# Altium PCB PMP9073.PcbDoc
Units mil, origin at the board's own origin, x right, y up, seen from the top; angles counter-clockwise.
Board outline 2100 x 1500 mil, 2 copper layers (Top Layer, Bottom Layer), stack 62 mil thick; 21 components, 11 nets, 42 pads, 0 vias.
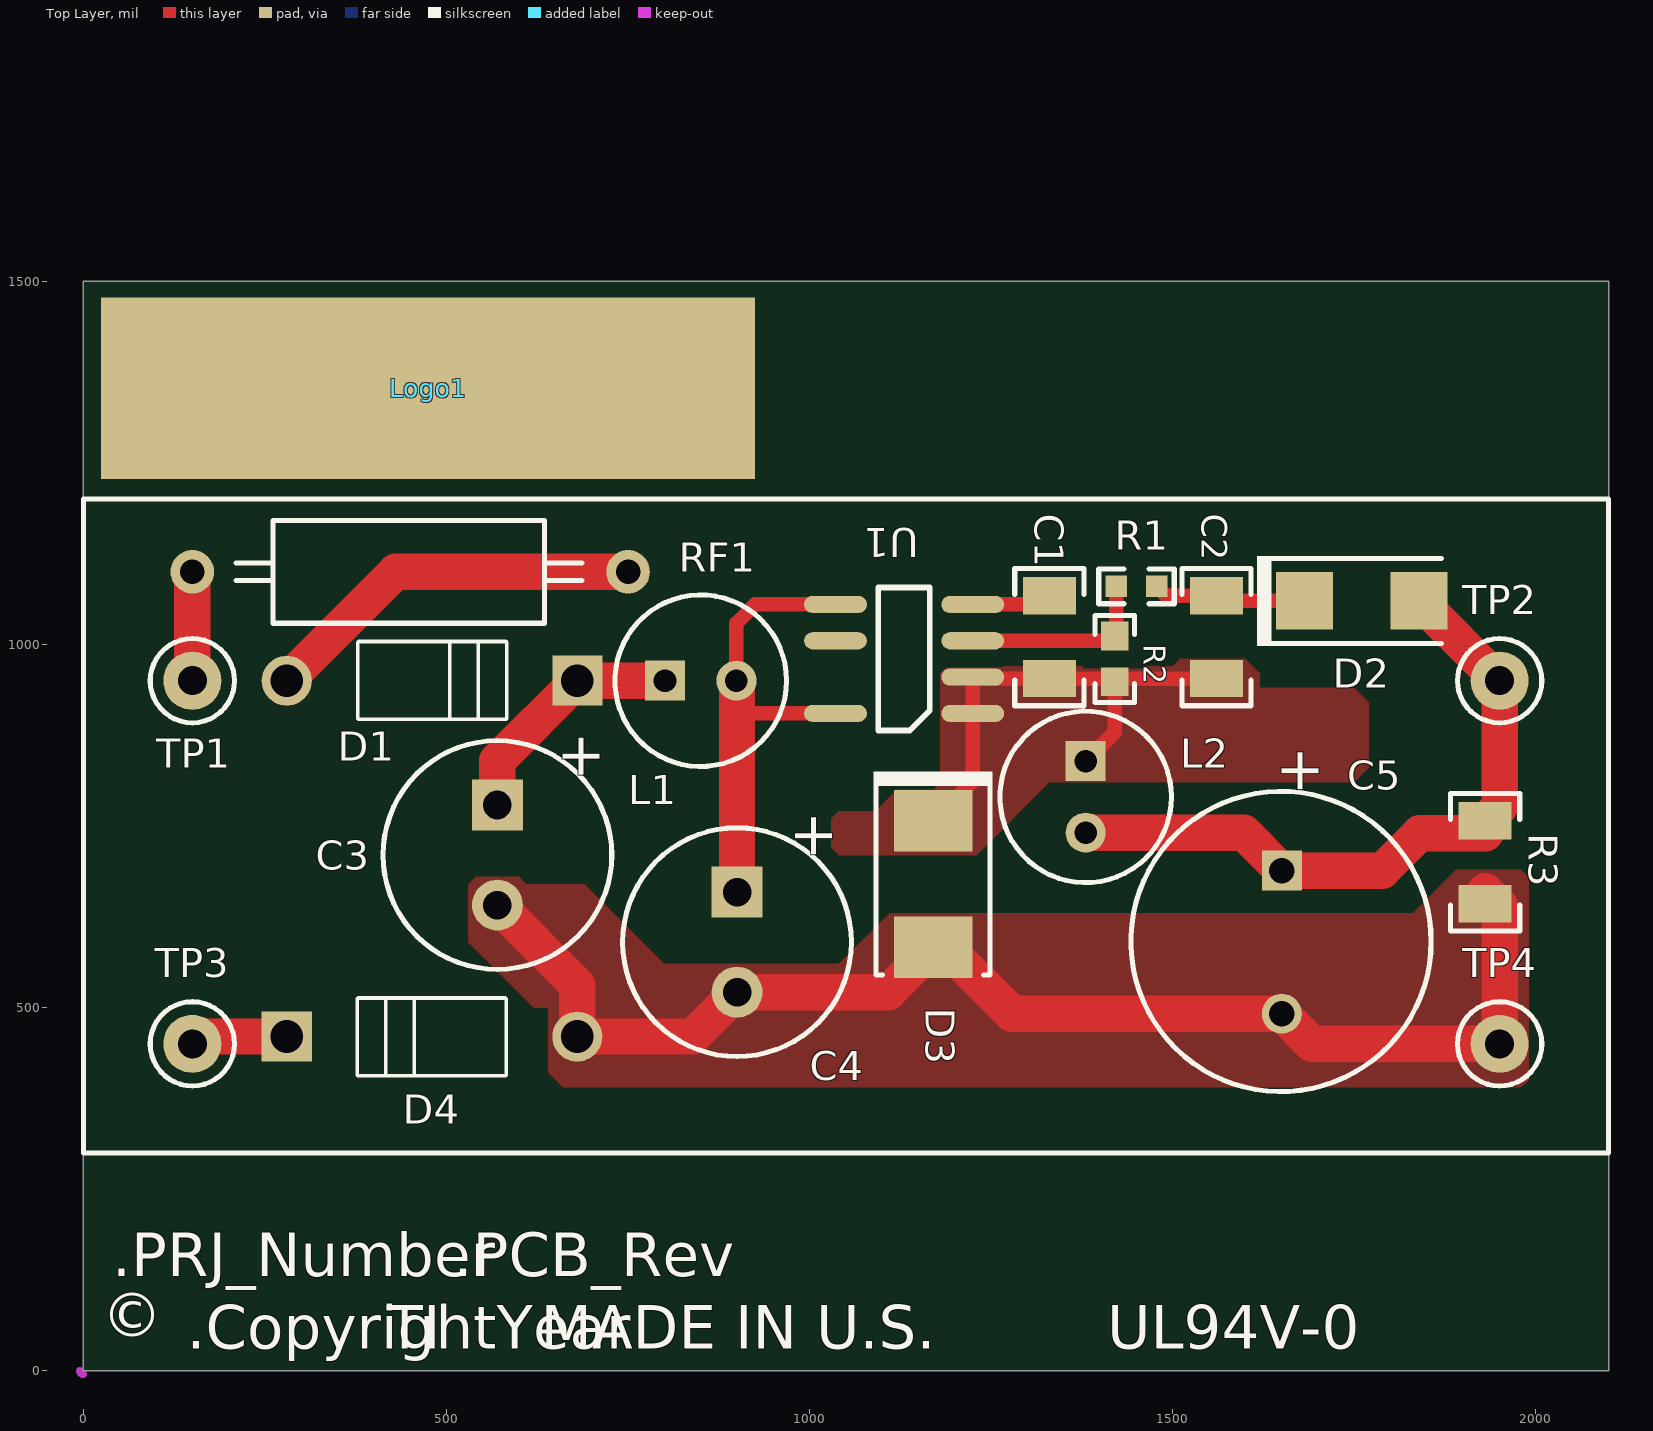
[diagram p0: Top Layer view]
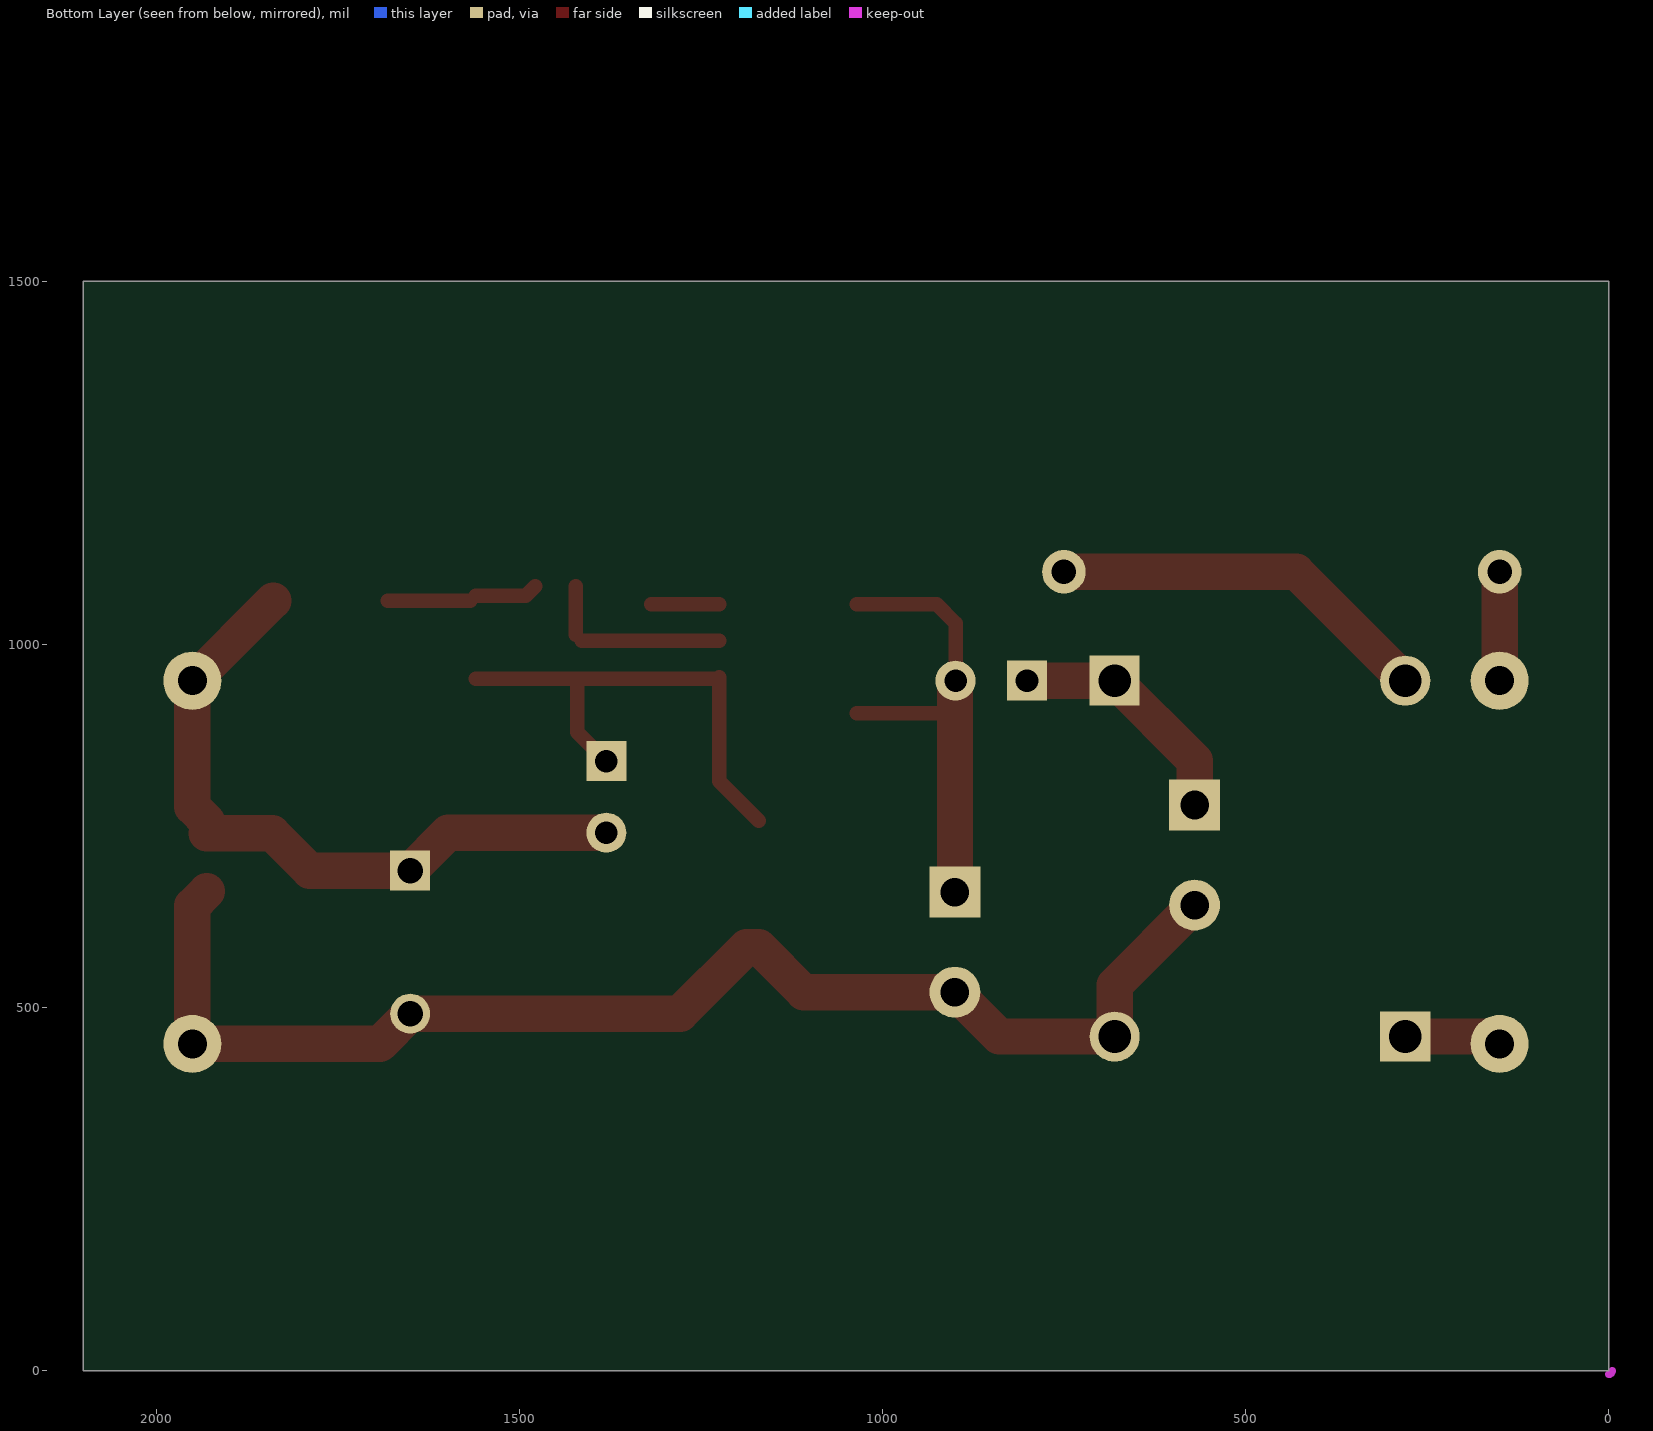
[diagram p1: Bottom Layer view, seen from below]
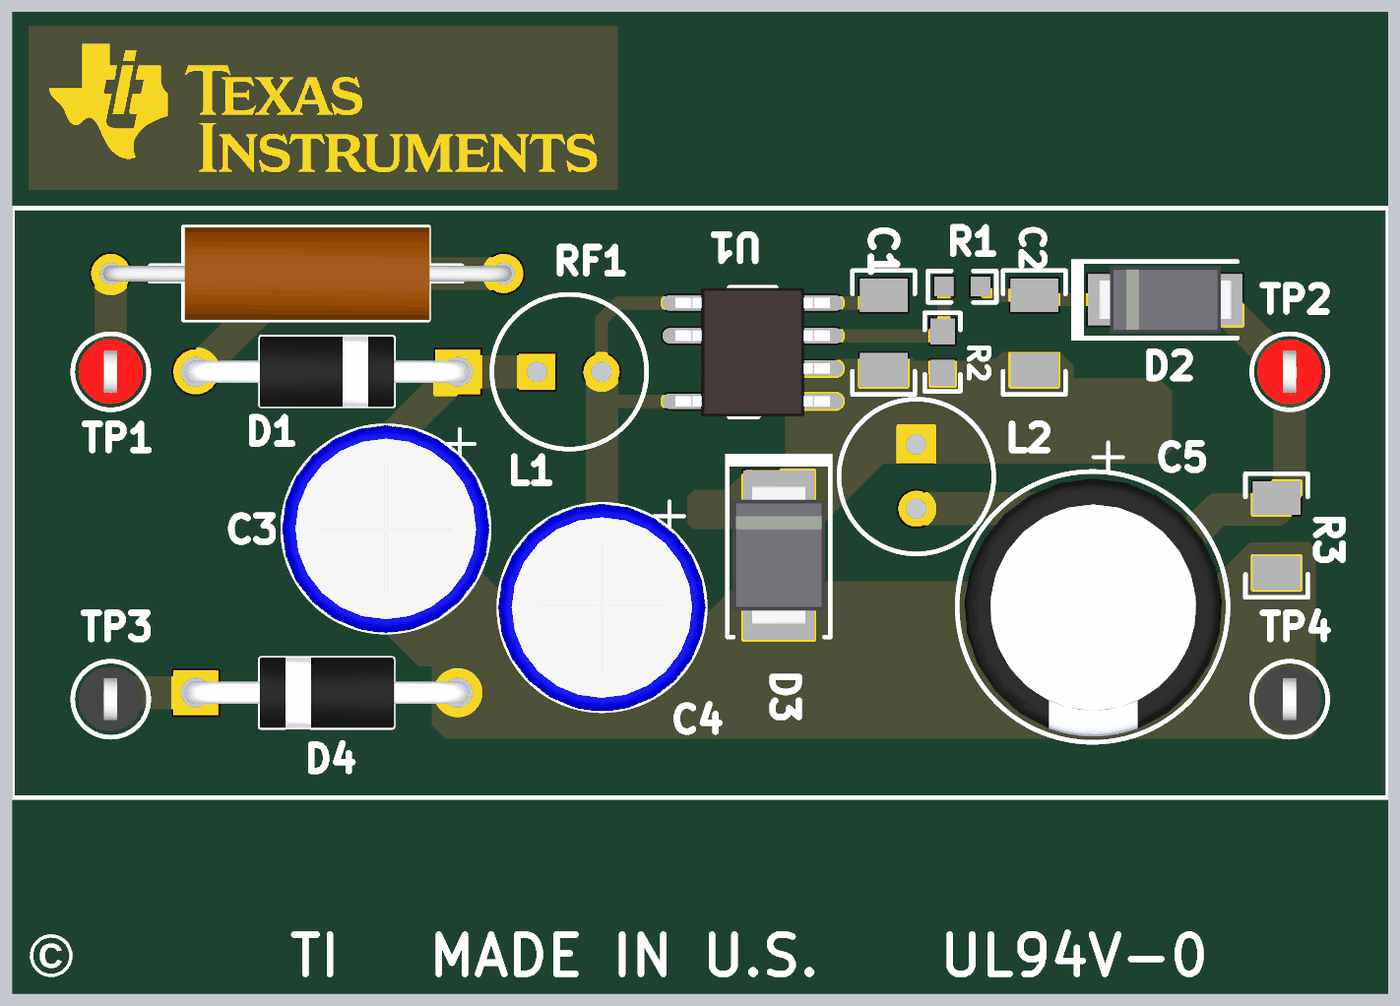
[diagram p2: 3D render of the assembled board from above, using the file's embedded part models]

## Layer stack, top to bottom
Top Layer: signal copper 1.4
Dielectric: core 59.2, FR-4, Dk 4.8
Bottom Layer: signal copper 1.4

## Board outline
0,0 2100,0 2100,1500 0,1500

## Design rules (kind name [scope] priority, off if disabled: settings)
AcuteAngle [All] p1: minimum=4.50000000000000E+0001 checktracksonly=FALSE
AssemblyTestPointUsage [All] p1: valid=2
Clearance Clearance_BoardEdge_MountingHoles [OnCopper and InComponentClass('Mounting Holes') vs IsKeepOut] p1: gap=40
Clearance Clearance_BoardEdge_Poly [OnCopper and InPoly vs IsKeepOut] p2: gap=25
Clearance Clearance_BoardEdge [OnCopper and Not InComponentClass('Logo') and not InComponentClass('FiducialMark') and not InRegion(1000,500,4000,800) and Not IsKeepout vs IsKeepOut] p3: gap=75
Clearance Clearance_Poly [InPolygon] p4: gap=25
Clearance [All] p5: gap=8
ComponentClearance ComponentClearance_Logo [InComponentClass(Logo)] p1: gap=50 collisioncheckmode=3 verticalgap=10 showdistances=FALSE
ComponentClearance ComponentClearance_ScrewToNut [(HasFootprint('NY PMS 440 0025 PH')) vs (HasFootprint('Keystone_1902C'))] p2: gap=5 collisioncheckmode=3 verticalgap=10 showdistances=FALSE
ComponentClearance ComponentClearance_MountingHoles [InComponentClass('Mounting Holes')] p3: gap=2 collisioncheckmode=3 verticalgap=100000 showdistances=FALSE
ComponentClearance ComponentClearance_SmallPassives [HasFootprint('0201*') or HasFootprint('0402*') or HasFootprint('0508') or HasFootprint('0603*') or HasFootprint('0612') or HasFootprint('0805*') or HasFootprint('0815*') or HasFootprint('0830*') or HasFootprint('1206*') or HasFootprint('1210*') or HasFootprint('1808*') or HasFootprint('1812*') or HasFootprint('1825*') or HasFootprint('2010*') or HasFootprint('2220*') or HasFootprint('2225*') or HasFootprint('2512*') or HasFootprint('2728*') or HasFootprint('3518*') vs HasFootprint('0201*') or HasFootprint('0402*') or HasFootprint('0508') or HasFootprint('0603*') or HasFootprint('0612') or HasFootprint('0805*') or HasFootprint('0815*') or HasFootprint('0830*') or HasFootprint('1206*') or HasFootprint('1210*') or HasFootprint('1808*') or HasFootprint('1812*') or HasFootprint('1825*') or HasFootprint('2010*') or HasFootprint('2220*') or HasFootprint('2225*') or HasFootprint('2512*') or HasFootprint('2728*') or HasFootprint('3518*')] p4: gap=20 collisioncheckmode=3 verticalgap=10 showdistances=FALSE
ComponentClearance ComponentClearance_THtoSMT [IsThruComponent vs IsSMTComponent] p5: gap=20 collisioncheckmode=3 verticalgap=10 showdistances=FALSE
ComponentClearance ComponentClearance_THtoTH [IsThruComponent vs IsThruComponent] p6: gap=20 collisioncheckmode=3 verticalgap=20 showdistances=FALSE
ComponentClearance [All] p7: gap=40 collisioncheckmode=3 verticalgap=10 showdistances=FALSE
DiffPairsRouting [All] p1: maxlimit=100 minlimit=10 mostfreqgap=10 maxuncoupledlength=1000
FabricationTestPointUsage TestPointUsage [All] p1: valid=2 allowmultiple=FALSE
FabricationTestpoint Testpoint [All] p1: side=3 testpointundercomponent=TRUE minsize=40 maxsize=100 preferedsize=60 minholesize=0 maxholesize=40 preferedholesize=32 testpointgrid=1 allowsidetop=TRUE allowsidebottom=TRUE usegrid=TRUE gridtolerance=0.01
FanoutControl Fanout_LCC [IsLCC] p1: bgadir=Out bgaviamode=Centered fanoutstyle=Auto fanoutdirection=Alternating viagrid=1 // Fanout_LCC (Default Rule)
FanoutControl Fanout_BGA [IsBGA] p2: bgadir=Out bgaviamode=Centered fanoutstyle=Auto fanoutdirection=Alternating viagrid=1 // Fanout_BGA (Default Rule)
FanoutControl Fanout_Default [All] p4: bgadir=Out bgaviamode=Centered fanoutstyle=Auto fanoutdirection=Alternating viagrid=1 // Fanout_Default (Default Rule)
FanoutControl Fanout_Small [(CompPinCount < 5)] p5: bgadir=Out bgaviamode=Centered fanoutstyle=Auto fanoutdirection=OutThenIn viagrid=1 // Fanout_Small (Default Rule)
HoleSize [All] p1: absolutevalues=TRUE maxlimit=251 minlimit=8 maxpercent=80.000 minpercent=20.000
MinimumAnnularRing [All] p1: minimumring=9
MinimumSolderMaskSliver MinimumSolderMaskSliver_Logo [InComponentClass('Logo') vs InComponentClass('Logo')] p1: minsoldermaskwidth=0.7
MinimumSolderMaskSliver [All] p2: minsoldermaskwidth=4
PlaneConnect [All] p1: planeconnectstyle=Relief reliefexpansion=10 reliefentries=4 reliefconductorwidth=10 reliefairgap=10
PolygonConnect PolygonConnect_1 [All vs IsNamedPolygon('C1_2_T') Or  IsNamedPolygon('C4_1_T') Or  IsNamedPolygon('GND_T')] p1: connectstyle=Direct reliefconductorwidth=10 reliefentries=4 polygonreliefangle="90 Angle" airgapwidth=10
PolygonConnect [All] p2: connectstyle=Relief reliefconductorwidth=10 reliefentries=4 polygonreliefangle="90 Angle" airgapwidth=10
RoutingVias [All] p1: holewidth=16 width=34 viastyle="Through Hole" minholewidth=8 minwidth=26 maxholewidth=40 maxwidth=65
SMDToCorner [All] p1: distance=30000
SilkToSilkClearance [All] p1: silktosilkclearance=5
SilkscreenOverComponentPads [All] p1: minsilkscreentomaskgap=5
SolderMaskExpansion [All] p1: expansion=3
Width [All] p1: maxlimit=100 minlimit=6 preferedwidth=10 checkconnectedcopper=TRUE
14 further rules are at their usual default settings.

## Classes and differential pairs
component class Logo: Logo1
component class PMP9073_02: !PCB1 Logo1

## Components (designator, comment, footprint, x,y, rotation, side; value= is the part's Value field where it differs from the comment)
C1 "12065C223KAT2A" 1206 1330,1010 r270 top
C2 "12065C104JAT2A" 1206 1560,1010 r270 top
C3 "400AX6R8M8x11" CAPPRD350W60D800H1100 570,710 r270 top
C4 "400AX6R8M8x11" CAPPRD350W60D800H1100 900,590 r270 top
C5 "EEU-FR1E151B" CAPPRD500W60D1000H1250 1650,590 r270 top
D1 "1N4007" DO-41 480,950 r180 top
D2 "ES1J-TP" SMA 1760,1060 r0 top
D3 "MURS160-13-F" SMB 1170,670 r270 top
D4 "1N4007" DO-41 480,460 r0 top
L1 "7447462102" IND_WE-TI_XS 850,950 r0 top
L2 "744743102" IND_WE-TI_XS 1380,790 r270 top
Logo1 "Texas Instruments" TI_Stacked_SolderMask_Small 474.49,1352.71 r0 top
R1 "CRCW0603110KFKEA" 0603_HV 1450,1080 r0 top
R2 "CRCW060310K0FKEA" 0603 1420,980 r90 top
R3 "CRCW120612K0JNEA" 1206 1930,700 r90 top
RF1 "FKN1WSJR-52-4R7" RESAD1524W55L900D150 450,1100 r180 top
TP1 "5000" Keystone5000 150,950 r0 top
TP2 "5000" Keystone5000 1950,950 r0 top
TP3 "5001" Keystone5001 150,450 r0 top
TP4 "5001" Keystone5001 1950,450 r0 top
U1 "UCC28880D" D0007A_N 1130,980 r180 top

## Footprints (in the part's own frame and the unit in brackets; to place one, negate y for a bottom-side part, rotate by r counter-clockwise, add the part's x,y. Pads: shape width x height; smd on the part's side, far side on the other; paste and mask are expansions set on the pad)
0603 [mm] "0603 from SM-752 data"
  rect 1x0.95 smd: 1(-0.8,0) 2(0.8,0)
  silkscreen extent -1.52,-0.69 1.52,0.69, body extent -0.87,-0.47 0.87,0.47, height 0.85
0603_HV [mil] "Ernesto recommended land pattern.  26 mil between pads."
  rect 30x30 smd: 1(-28,0) 2(28,0)
  silkscreen extent -52,-24 52,24, body extent -34,-19 34,19, height 33
1206 [mm] "1206 from SM-752 data"
  rect 1.3x1.85 smd: 1(-1.45,0) 2(1.45,0)
  silkscreen extent -2.4,-1.21 2.4,1.21, body extent -1.7,-0.9 1.7,0.9, height 1.35
CAPPRD350W60D800H1100 [mm] "Capacitor, Alum, 8x11mm"
  rect 1.78x1.78 hole 1: 1(-1.75,0)
  round 1.78 hole 1: 2(1.75,0)
  silkscreen extent -4,-4 4,4, body extent -4.03,-4.03 4.03,4.02, height 11.79
CAPPRD500W60D1000H1250 [mm] "Capacitor, Electrolytic, Radial; Body 10 x 12.5 mm (Dia.xH typ); Pin Spacing 5 mm (typ)"
  rect 1.4x1.4 hole 0.889: 1(-2.5,0)
  round 1.4 hole 0.889: 2(2.5,0)
  silkscreen extent -5.27,-5.27 5.22,5.22, body extent -5,-4.99 5,4.99, height 14.12
D0007A_N [mm] "SOIC, 7-Leads, Body 4.9x3.9mm, Pitch 1.27mm, IPC Medium Density"
  oval 2.2x0.6 smd: 1(-2.4,1.905) 2(-2.4,0.635) 3(-2.4,-0.635) 4(-2.4,-1.905) 5(2.4,-1.905) 6(2.4,-0.635) 8(2.4,1.905)
  silkscreen extent -0.9,-2.5 0.9,2.5, body extent -3,-2.5 3,2.5, height 1.54
DO-41 [mm] "diode"
  rect 1.75x1.75 hole 1.15: 1(-5.08,0)
  round 1.75 hole 1.15: 2(5.08,0)
  silkscreen extent -2.62,-1.37 2.59,1.35, body extent -5.51,-1.36 5.51,1.36, height 2.72
IND_WE-TI_XS [mm] "Wurth WE-TI 5075"
  rect 1.4x1.4 hole 0.787: 1(-1.25,0)
  round 1.4 hole 0.787: 2(1.25,0)
  silkscreen extent -3,-3 3,3, body extent -3.01,-3.01 3.01,3.01, height 8.5
Keystone5000 [mil] "For Keystone 500x miniature loop terminals"
  round 80 hole 40: 1(0,0)
  silkscreen extent -58,-58 58,58, body extent -49,-49 49,49, height 182
Keystone5001 [mil] "For Keystone 500x miniature loop terminals"
  round 80 hole 40: 1(0,0)
  silkscreen extent -58,-58 58,58, body extent -49,-49 49,49, height 182
RESAD1524W55L900D150 [mil]
  round 60 hole 33.46: 1(-300,0) 2(300,0)
  silkscreen extent -236,-71 240,71, body extent -312,-71 312,71, height 141
SMA [mm] "Molded Diode, 2-Leads, Body 4.3x2.6mm, IPC Medium Density, based on OnSemi component dimensions and land pattern"
  rect 2x2 smd: 1(-2,0) 2(2,0)
  silkscreen extent -3.66,-1.57 2.79,1.57, body extent -2.6,-1.3 2.6,1.3, height 2.42
SMB [mil] "Molded Diode, 2-Leads, Body 5.4x3.6mm, IPC Medium Density, based on OnSemi component dimensions"
  rect 85x107.99 smd: 1(-87.01,0) 2(87.01,0)
  silkscreen extent -155,-82 125,82, body extent -106,-71 106,71, height 91
TI_Stacked_SolderMask_Small [mil]
  rect 900x250 smd paste-125 mask-125: 0(0,0)

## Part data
C1: "CAP, CERM, 0.022uF, 50V, +/-10%, X7R, 1206"
C2: "CAP, CERM, 0.1uF, 50V, +/-5%, X7R, 1206"
C3 C4: "CAP, AL, 6.8uF, 400V, +/-20%, TH"
C5: library part UVY2G4R7MPD, "CAP ALUM 150UF 25V 20% RADIAL"
D1 D4: "Diode, P-N, 1000V, 1A, TH"
D2: library part ES1D-13-F, "DIODE FAST REC 600V 1A DO214AC"
D3: "Diode, Ultrafast, 600V, 1A, SMB"
L1: "Inductor, Unshielded Drum Core, Ferrite, 1mH, 0.25A, 4.38 ohm, TH"
L2: library part 7447462102, "Inductor, INDUCTOR 1000UH .42A RADIAL"
Logo1: library part TI_Logo, "Texas Instrument Corporate Signature"
R1: "RES, 110k ohm, 1%, 0.1W, 0603"
R2: "RES, 10.0k ohm, 1%, 0.1W, 0603"
R3: "RES, 12k ohm, 5%, 0.25W, 1206"
RF1: "RES, 4.7 ohm, 5%, 1W, Fusible, TH"
TP1 TP2: "Test Point, Miniature, Red, TH"
TP3 TP4: "Test Point, TH, Miniature, Black"
U1: "Low Quiescent Current Switcher IC for AC/DC Power Supplies, D0007A"

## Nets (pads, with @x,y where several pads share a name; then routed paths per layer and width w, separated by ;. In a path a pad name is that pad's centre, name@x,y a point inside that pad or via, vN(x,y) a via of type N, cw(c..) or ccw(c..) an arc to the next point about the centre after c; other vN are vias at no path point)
GND: C3.2 C4.2 C5.2 D3.2 D4.2 R3.1 TP4.1 | length 1821
  Top Layer w50: C3.2 680,531.1 D4.2 838.9,460 C4.2 1108.11,521.1 D3.2 1187.01,582.99 1278.43,491.57 C5.2 1691.57,450 TP4.1 1950,640 R3.1@1930,660
NetC1_1: C1.1 U1.4 | length 93.4
  Top Layer w20: U1.4 C1.1@1317.91,1055
NetC1_2: C1.2 C2.2 D3.1 L2.1 R2.1 U1.1 U1.2 | length 679.8
  Top Layer w20: D3.1 1224.49,811.5 U1.1 U1.2 ; U1.2@1226.57,952.91 C1.2 C2.2 ; L2.1 1420,879.21 R2.1
NetC2_1: C2.1 D2.1 R1.2 | length 201.5
  Top Layer w20: R1.2 1490.91,1067.09 C2.1 ; C2.1@1567.09,1060 D2.1
NetC3_1: C3.1 D1.1 L1.1 | length 337.5
  Top Layer w50: C3.1 570,840 D1.1 L1.1
NetC4_1: C4.1 L1.2 U1.5 U1.8 | length 648.1
  Top Layer w20: L1.2 899.21,1029.21 925,1055 U1.5 ; 905,905 U1.8
  Top Layer w50: L1.2 900,949.21 C4.1
NetC5_1: C5.1 D2.2 L2.2 R3.2 TP2.1 | length 951.8
  Top Layer w50: L2.2 1597.64,740.79 C5.1 1788.43,688.43 1840,740 R3.2@1930,740 ; D2.2 1948.74,950 TP2.1 1950,776.37 R3.2@1930,756.37
NetD1_2: D1.2 RF1.1 | length 532.1
  Top Layer w50: D1.2 430,1100 RF1.1
NetD4_1: D4.1 TP3.1 | length 120
  Top Layer w50: TP3.1@160,460 D4.1
NetR1_1: R1.1 R2.2 U1.3 | length 255.5
  Top Layer w20: U1.3 R2.2@1413.5,1005 ; R2.2@1422,1013.5 R1.1
NetRF1_2: RF1.2 TP1.1 | length 150
  Top Layer w50: TP1.1 RF1.2
pads on no net: Logo1.0 U1.6

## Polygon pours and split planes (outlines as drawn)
NetC1_2 on Top Layer "C1_2_T" (solid, pour order 4): 1040,710 1030,720 1030,760 1040,770 1090,770 1120,800 1170.24,800 1180,809.76 1180,960 1190,970 1280,970 1290,980 1380,980 1390,970 1500,970 1510,980 1600,980 1620,960 1620,940 1750,940 1770,920 1770,830 1750,810 1330,810 1230,710
GND on Top Layer "GND_T" (solid, pour order 6): 530,670 540,680 600,680 610,670 690,670 800,560 1040,560 1110,630 1830,630 1890,690 1980,690 1990,680 1990,400 1980,390 660,390 640,410 640,500 620,500 530,590

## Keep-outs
Keep-Out Layer:
  lines w10: -5,0 ccw(c0,0) 0,-5 ; -5,0 ccw(c0,0) 0,-5 ; -5,0 ccw(c0,0) 0,-5 ; -5,0 ccw(c0,0) 0,-5 ; -5,0 ccw(c0,0) 0,-5 ; -5,0 ccw(c0,0) 0,-5
  text ".Layer_Name" at 577,-858.49 h60

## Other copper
Top Layer:
  text ".Layer_Name" at 577,-858.49 h60
Bottom Layer:
  text ".Layer_Name" at 577,-858.49 h60

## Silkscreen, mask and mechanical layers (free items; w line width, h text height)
Top Overlay:
  lines w7: 0,300 2100,300 2100,1200 0,1200 0,300
  text ".PRJ_Number" at 40,130 h60
  text ".PCB_Rev" at 510,130 h60
  text ".CopyrightYear" at 142,30 h60
  text "TI" at 418,30 h60
  text "MADE IN U.S." at 630,30 h60
  text "UL94V-0" at 1410,30 h60
  text "©" at 25,26.48 h105
  text ".Layer_Name" at 577,-858.49 h60
Bottom Overlay:
  text ".Layer_Name" at 577,-858.49 h60
Top Paste:
  text ".Layer_Name" at 577,-858.49 h60
Bottom Paste:
  text ".Layer_Name" at 577,-858.49 h60
Top Solder:
  text ".Layer_Name" at 577,-858.49 h60
  text ".Layer_Name" at 577,-858.49 h60
Bottom Solder:
  text ".Layer_Name" at 577,-858.49 h60
Drill Guide:
  text ".Layer_Name" at 577,-858.49 h60
M1 Board Outline:
  the board outline again, w10
  text ".Layer_Name" at 577,-858.49 h60
M2 Board Dimensions:
  rectangle: -0.5,-285.5 124.5,-160.5
  rectangle: 124.5,-410.5 499.5,-285.5
  lines w7: -0.5,-285.5 999.5,-285.5 ; 124.5,-410.5 124.5,-160.5 ; 249.5,-410.5 249.5,-160.5 ; 499.5,-410.5 499.5,-160.5 ; 749.5,-410.5 749.5,-160.5 ; -0.5,-410.5 999.5,-410.5 999.5,-160.5 -0.5,-160.5 -0.5,-410.5
  lines w10: -0.5,-475.5 -0.5,-455.5 ; 59.5,-485.5 -0.5,-465.5 ; 59.5,-445.5 -0.5,-465.5 ; 223.58,-465.5 -0.5,-465.5 ; 775.42,-465.5 999.5,-465.5 ; 939.5,-485.5 999.5,-465.5 ; 939.5,-445.5 999.5,-465.5 ; 999.5,-475.5 999.5,-455.5
  text "1000 (mil)" at 233.58,-501.49 h60
  text ".Layer_Name" at 577,-858.49 h60
M3 3D STEP Top:
  text ".Layer_Name" at 577,-858.49 h60
M4 3D STEP Bottom:
  text ".Layer_Name" at 577,-858.49 h60
M5 Assembly Top:
  lines w7: 5139,110.5 6264,110.5 ; 5139,233 6261.5,233 ; 5454,-9.5 5454,353 ; 5839,-9.5 5139,-9.5 ; 5839,353 5139,353 ; 5139,-9.5 6264,-9.5 6264,353 5139,353 ; 5139,-9.5 5139,353
  lines w10: -292,-930.17 6308,-930.17 ; -292,-726.83 6310,-726.83 ; -292,-523.5 -292,-1133.5 3713,-1133.5 6310,-1133.5 6310,-523.5 -291.5,-523.5 -291.5,-1133.5 1284,-1133.5 ; 2173,-1133.5 2173,-523.5 ; 3440,-726.83 3440,-523.5 ; 4280,-726.83 4280,-523.5 ; 4902,-1140 4902,-937.17
  text "TABLE 1" at 5526.5,388 h40
  text "Variant" at 5164,278 h40
  text "Label text" at 5599,278 h40
  text "001" at 5231.5,158 h40
  text "ChangeMe!" at 5509,155.5 h40
  text "002" at 5231.5,33 h40
  text "ChangeMe!" at 5504,30.5 h40
  text "COMPONENTS MARKED 'DNP' SHOULD NOT BE POPULATED." at 1153.5,-318.5 h60
  text "ASSEMBLY VARIANT:" at 1153,-434 h60
  text ".VariantName" at 2189,-434 h60
  text "PCB VIEWED FROM TOP SIDE" at -228.5,-655.67 h60
  text "BOARD #:" at 2248,-655.67 h60
  text ".PRJ_Number" at 2793.5,-655.67 h60
  text "REV:" at 3638,-655.67 h60
  text ".PCB_Rev" at 3929.5,-655.67 h60
  text "SVN REV:" at 4476,-655.67 h60
  text ".VersionControl_RevNumber" at 4982,-655.67 h60
  text "IGNORE ->" at -228.5,-858.49 h60
  text "PLOT NAME =" at -228.5,-1064.34 h60
  text ".plot_File_Name" at 577,-1064.34 h60
  text "GENERATED    :" at 2250,-1064.34 h60
  text ".Print_Date" at 3119.5,-1064.34 h60
  text ".Print_Time" at 3848.5,-1064.34 h60
  text "TEXAS INSTRUMENTS" at 5113,-1064.34 h60
M6 Assembly Bottom:
  lines w10: -292.5,-727.33 6309.5,-727.33 ; -290.5,-930.67 6309.5,-930.67 ; 1115.5,-1140.5 1115.5,-937.67 ; 1737.5,-727.33 1737.5,-524 ; 2577.5,-727.33 2577.5,-524 ; 3844.5,-1134 3844.5,-524 ; 4733.5,-1134 6309,-1134 6309,-524 -292.5,-524 -292.5,-1134 2304.5,-1134 6309.5,-1134 6309.5,-524
  text "COMPONENTS MARKED 'DNP' SHOULD NOT BE POPULATED." at 6102,-318 h60
  text ".VariantName" at 5058,-434 h60
  text "ASSEMBLY VARIANT:" at 6097,-434 h60
  text ".VersionControl_RevNumber" at 1035.5,-656.17 h60
  text "SVN REV:" at 1541.5,-656.17 h60
  text ".PCB_Rev" at 2088,-656.17 h60
  text "REV:" at 2379.5,-656.17 h60
  text ".PRJ_Number" at 3224,-656.17 h60
  text "BOARD #:" at 3769.5,-656.17 h60
  text "PCB VIEWED FROM BOTTOM SIDE" at 6246,-656.17 h60
  text "IGNORE ->" at 2547.85,-858.49 h60
  text "TEXAS INSTRUMENTS" at 904.5,-1064.84 h60
  text ".Print_Time" at 2169,-1064.84 h60
  text ".Print_Date" at 2898,-1064.84 h60
  text "GENERATED    :" at 3767.5,-1064.84 h60
  text ".plot_File_Name" at 5440.5,-1064.84 h60
  text "PLOT NAME =" at 6246,-1064.84 h60
M9 Title Sheet:
  drawing of 57 lines, arcs and shapes, not listed
  text "1" at 739.84,8036.5 h70
  text "2" at 3235.5,8036.5 h70
  text "3" at 5724.84,8036.5 h70
  text "4" at 8231.51,8036.5 h70
  text "5" at 10730.5,8036.5 h70
  text "6" at 13235.5,8036.5 h70
  text "A" at -416.5,6893.5 h70
  text "A" at 14383.5,6893.5 h70
  text "B" at -416.5,4513.5 h70
  text "B" at 14383.5,4513.5 h70
  text "C" at -416.5,2138.5 h70
  text "C" at 14383.5,2138.5 h70
  text "PROJECT TITLE:" at 11343.5,277.5 h45
  text ".PRJ_Title" at 11393.5,144.17 h70
  text "DESIGNED FOR:" at 11343.5,-23.5 h45
  text ".PRJ_Customer" at 11393.5,-163.5 h70
  text "D" at -416.5,-231.5 h70
  text "D" at 14383.5,-231.5 h70
  text "FILE NAME:" at 11343.5,-323.5 h45
  text ".PCB_File_Name_No_Path" at 11393.5,-443.5 h70
  text "Texas Instruments (TI) and/or its licensors do not warrant the accuracy or completeness of this specification" at 6374,-605.34 h45
  text "ENGINEER:" at 11343.5,-613.5 h45
  text "LAYOUT BY:" at 12848.5,-613.5 h45
  text "or any information contained therein. TI and/or its licensors do not warrant that this design will meet" at 6329.01,-718 h45
  text ".PRJ_Engineer" at 11393.5,-768.49 h70
  text ".PCB_Layout" at 12899,-768.49 h70
  text "the specifications, will be suitable for your application or fit for any particular purpose, or will operate in" at 6329.01,-830.67 h45
  text ".Layer_Name" at 577,-858.49 h60
  text "ALTIUM DESIGNER VERSION:" at 12848.5,-923.5 h45
  text "an implementation. TI and/or its licensors do not warrant that the design is production worthy. You should" at 6329.01,-943.33 h45
  text "completely validate and test your design implementation to confirm the system functionality for your application." at 6374,-1056 h45
  text ".print_Scale" at 11393.5,-1056.83 h70
  text ".Application_BuildNumber" at 12899,-1056.83 h70
  text "1" at 739.84,-1263.5 h70
  text "2" at 3235.5,-1263.5 h70
  text "3" at 5724.84,-1263.5 h70
  text "4" at 8231.51,-1263.5 h70
  text "5" at 10730.5,-1263.5 h70
  text "6" at 13235.5,-1263.5 h70
M10 Fab Notes:
  drawing of 212 lines, arcs and shapes, not listed
  text "DESIGN INFORMATION" at 12381.02,6810 h60
  text "(REFER ALSO ARRAY/PANEL PROFILING INFORMATION)" at 12019.46,6648.29 h60
  text "BOARD SIZE" at 11333.46,6644 h60
  text "1500MIL" at 11795.78,6516.18 h60
  text "X" at 12301.46,6516.18 h60
  text "2100MIL" at 12532.78,6516.18 h60
  text "Number of Layers :" at 11736.46,6319 h60
  text "1" at 12831.27,6309 h60
  text "MIN. TRACK WIDTH:" at 11736.46,6180 h60
  text "10" at 12832.7,6180 h60
  text "MIL" at 12987.46,6180 h60
  text "MIN. CLEARANCE:" at 11736.46,6048 h60
  text "10" at 12832.7,6048 h60
  text "MIL" at 12987.46,6048 h60
  text "MIN. VIA PAD SIZE:" at 11736.46,5916 h60
  text "10" at 12802.71,5916 h60
  text "MIL" at 12987.46,5916 h60
  text "0.05mm (2MIL)" at 12431.46,5774.29 h60
  text "MINIMUM ANNULAR RING" at 11407.23,5770 h60
  text "EXTERNAL" at 13139.46,5770 h60
  text "PER" at 11607.23,5652 h60
  text "IPC-D-275 CLASS 2 LEVEL C" at 11827.23,5652 h60
  text "MIL, HOLES" at 13315.46,5539.71 h60
  text "+/-" at 12923,5539 h60
  text "+/-" at 13777,5539 h60
  text "REGISTRATION TOLERANCES:" at 11407.23,5534 h60
  text "METAL" at 12607,5534 h60
  text "5" at 13183.2,5534 h60
  text "3" at 14016.2,5534 h60
  text "MIL" at 14132.46,5534 h60
  text "MATERIAL:" at 11332.46,5324.54 h60
  text "FR-4 High Tg" at 12318.9,5184.21 h60
  text "FR-408" at 11753.46,5175.64 h60
  text "X" at 12165.46,5175.64 h60
  text "OTHER" at 13241.46,5175.64 h60
  text "62 MIL (1.6mm) +/-10%" at 12073.56,5012.92 h60
  text "THICKNESS:" at 11407.23,5008.64 h60
  text "X" at 11945.4,5008.64 h60
  text "OTHER" at 13358.46,5008.64 h60
  text "TOLERANCE:" at 11407.23,4850.64 h60
  text "X" at 12246.53,4850.64 h60
  text "ANSI IPC-6012 TYPE 3 CLASS 2" at 12433.48,4850.64 h60
  text "OTHER +/-" at 12433.46,4694.64 h60
  text "BOW & TWIST:" at 11407.23,4537.64 h60
  text "X" at 12246.53,4537.64 h60
  text "ANSI IPC-6012 TYPE 3 CLASS 2" at 12433.48,4537.64 h60
  text "OTHER +/-" at 12433.46,4379.13 h60
  text "COPPER THICKNESS (FINISHED):" at 11332.46,4243.64 h60
  text "1.4MIL (1oz)" at 12212.46,4090.92 h60
  text "2MIL (1.4oz)" at 12979.46,4090.92 h60
  text "2.8MIL (2oz)" at 13706.46,4090.92 h60
  text "OUTER:" at 11689.46,4086.64 h60
  text "X" at 12084,4086 h60
  text "X" at 13580,3940 h60
  text "1.4MIL (1oz)" at 12212.46,3933.92 h60
  text "2.8MIL (2oz)" at 12979.46,3933.92 h60
  text "N/A" at 13706,3934.29 h60
  text "INNER SIGNAL:" at 11400.38,3929.64 h60
  text "DRILLING:" at 11332.46,3790.64 h60
  text "REFERENCE:" at 11407.23,3673.64 h60
  text "X" at 12055.46,3673.64 h60
  text "AS SHOWN" at 12242.46,3673.64 h60
  text "X" at 12956.46,3673.64 h60
  text "NC_DRILL FILES" at 13093.46,3673.64 h60
  text "PTH MIN COPPER THICKNESS:" at 11407.23,3515.64 h60
  text "X" at 12757.46,3515.64 h60
  text "1MIL" at 12894.46,3515.64 h60
  text "OTHER" at 13391.46,3515.64 h60
  text "BOARD FINISH:" at 11332.46,3356.64 h60
  text "SILKSCREEN:" at 11487.68,3238.64 h60
  text "X" at 12436.46,3238.64 h60
  text "TOP" at 12562.46,3238.64 h60
  text "BOTTOM" at 13073.46,3238.64 h60
  text "SILKSCREEN COLOR:" at 11487.68,3071.64 h60
  text "X" at 12435.42,3071.64 h60
  text "WHITE" at 12562.46,3071.64 h60
  text "OTHER" at 13073.46,3071.64 h60
  text "SOLDER RESIST COLOR:" at 11487.68,2901.64 h60
  text "X" at 12055.42,2742.44 h60
  text "GREEN" at 12182.46,2742.44 h60
  text "BLUE" at 12773.46,2742.44 h60
  text "OTHER" at 13311.46,2742.44 h60
  text "IMMERSION GOLD (ENIG)" at 12393.46,2553.92 h60
  text "ENEPIG" at 13731,2550.64 h60
  text "SURFACE FINISH:" at 11332.46,2549.64 h60
  text "IMM. TIN/SILVER OR EQUIV" at 11662,2392.64 h60
  text "OTHER" at 13093.46,2392.64 h60
  text "X" at 11490,2390 h60
  text "ARRAY/PANEL:" at 11332.46,2213.64 h60
  text "CUT AND TRIM PER MECH LAYER 1" at 12393.46,2209.35 h60
  text "N.C. ROUTE" at 12393.46,2057.64 h60
  text "X" at 13072.46,2057.64 h60
  text "V. SCORE" at 13259.46,2057.64 h60
  text "CERTIFICATION:" at 11332.46,1920.64 h60
  text "MATERIALS AND WORKMANSHIP FOR ALL PCBS" at 12057.46,1920.64 h60
  text "TO MEET OR EXCEED THE REQUIREMENTS OF:" at 12057.46,1822.64 h60
  text "X" at 11683.96,1686.13 h60
  text "ANSI IPC-A-600F CLASS ->" at 11822.96,1686.13 h60
  text "X" at 13462.02,1686.13 h60
  text "2" at 13580.96,1686.14 h60
  text "1" at 13265.96,1684.64 h60
  text "3" at 13934.96,1684.64 h60
  text "X" at 11686.02,1526.64 h60
  text "UL 94V-0" at 11822.96,1526.64 h60
  text "X" at 12498.02,1526.64 h60
  text "RoHS" at 12634.96,1526.64 h60
  text "OTHER" at 13279.36,1526.64 h60
  text "PER ORDER" at 13676.42,1526.64 h60
  text "ADDITIONAL REQUIREMENTS:" at 11332.46,1385.64 h60
  text "MICROSECTION:" at 11407.23,1270.64 h60
  text "YES" at 12312.96,1270.64 h60
  text "REQUIRED" at 13174.46,1114.49 h60
  text "BARE BOARD ELEC. TEST:" at 11407.23,1111.64 h60
  text "NONE" at 12712.96,1111.64 h60
  text "PER ORDER" at 13766.46,1111.64 h60
  text "X" at 12590,1110 h60
  text "MANUFACTURER'S UL:" at 11407.23,954.64 h60
  text "RAIL" at 12572.96,950.35 h60
  text "METAL" at 13064.77,950.35 h60
  text "X" at 13440,950 h60
  text "SILK" at 13576.46,950.35 h60
  text ".Layer_Name" at 577,-858.49 h60
M11 Gerber Information:
  lines w10: -292,-930.17 6308,-930.17 ; -292,-726.83 6310,-726.83 ; -292,-523.5 -292,-1133.5 3713,-1133.5 6310,-1133.5 6310,-523.5 -291.5,-523.5 -291.5,-1133.5 1284,-1133.5 ; 2173,-1133.5 2173,-523.5 ; 3440,-726.83 3440,-523.5 ; 4280,-726.83 4280,-523.5 ; 4902,-1140 4902,-937.17
  text "ALL ARTWORK VIEWED FROM TOP SIDE" at -228.5,-655.67 h60
  text "BOARD #:" at 2248,-655.67 h60
  text ".PRJ_Number" at 2793.5,-655.67 h60
  text "REV:" at 3638,-655.67 h60
  text ".PCB_Rev" at 3929.5,-655.67 h60
  text "SVN REV:" at 4476,-655.67 h60
  text ".VersionControl_RevNumber" at 4982,-655.67 h60
  text "LAYER NAME =" at -228.5,-858.49 h60
  text "PLOT NAME =" at -228.5,-1064.34 h60
  text ".plot_File_Name" at 577,-1064.34 h60
  text "GENERATED    :" at 2250,-1064.34 h60
  text ".Print_Date" at 3119.5,-1064.34 h60
  text ".Print_Time" at 3848.5,-1064.34 h60
  text "TEXAS INSTRUMENTS" at 5113,-1064.34 h60
M12 Stackup:
  lines w6: 11330,7516.33 13810,7516.33 ; 11330,7624.83 13810,7624.83 ; 11270,7015 ccw(c11305,7015) 11305,6980 13835,6980 ccw(c13835,7015) 13870,7015 13870,7745 ccw(c13835,7745) 13835,7780 11305,7780 ccw(c11305,7745) 11270,7745 11270,7015
  text "Layer Stack Up Detail for: PMP9073.PcbDoc" at 11330,7658.22 h59
  text "Layer" at 11330,7584.33 h25
  text "Gerber" at 12203.47,7584.33 h25
  text "Copper" at 12737.92,7584.33 h25
  text "Dielectric" at 13313.19,7584.33 h25
  text "Name" at 11330,7534.33 h25
  text "Document" at 12203.47,7534.33 h25
  text "Thickness" at 12737.92,7534.33 h25
  text "Material" at 13313.19,7534.33 h25
  text "Top Solder Mask" at 11330,7438.33 h35
  text "(.GTS)" at 12203.47,7438.33 h35
  text "Solder Resist" at 13313.19,7438.33 h35
  text "Top Layer" at 11330,7338.33 h35
  text "(.GTL)" at 12203.47,7338.33 h35
  text "1.4mil" at 12737.92,7338.33 h35
  text "FR-4" at 13313.19,7288.33 h35
  text "Bottom Layer" at 11330,7238.33 h35
  text "(.GBL)" at 12203.47,7238.33 h35
  text "1.4mil" at 12737.92,7238.33 h35
  text "Bottom Solder Mask" at 11330,7138.33 h35
  text "(.GBS)" at 12203.47,7138.33 h35
  text "Solder Resist" at 13313.19,7138.33 h35
  text ".Layer_Name" at 577,-858.49 h60
M13 Component Bodies Top:
  text ".Layer_Name" at 577,-858.49 h60
M14 Component Bodies Bottom:
  text ".Layer_Name" at 577,-858.49 h60
M15 Courtyards Top:
  text ".Layer_Name" at 577,-858.49 h60
M16 Courtyards Bottom:
  text ".Layer_Name" at 577,-858.49 h60
Drill Drawing:
  text ".legend" at 5122.5,725.5 h60
  text "Drill Table" at 5147.5,540.5 h60
  text ".Layer_Name" at 577,-858.49 h60

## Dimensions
0,0 to 0,1500 on M2 Board Dimensions
0,0 to 2100,0 on M2 Board Dimensions
2100,300 to 2100,1200 on M2 Board Dimensions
